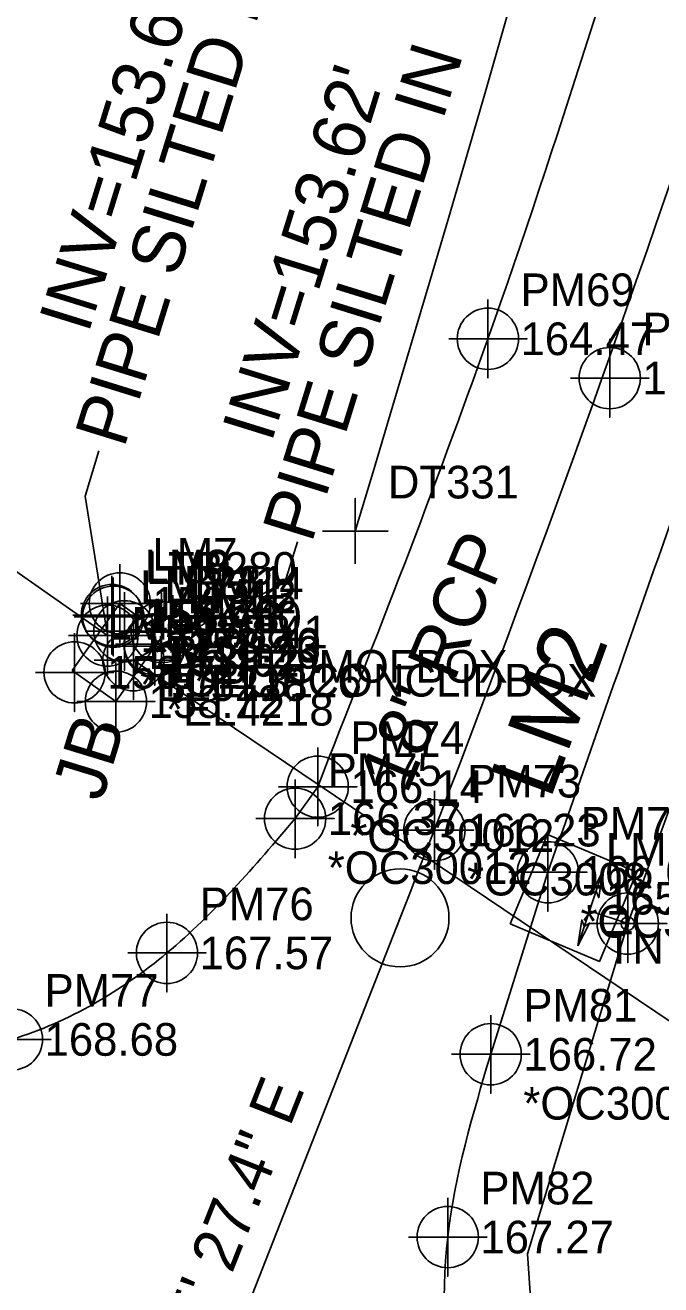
# Model space of a CAD drawing. Extents: x 2262665 to 2270527, y 505476 to 514960.
# Drawn here: x 2266229.4 to 2266278, y 509448.8 to 509545.3 of the extents above; entities that cross this region are included whole.
import ezdxf

# ---------------------------------------------------------------- set-up
doc = ezdxf.new("R2010")
doc.units = 0
for name, color, linetype in [('CTL Secondary Horizontal and Vertical CELL', 7, 'Continuous'), ('CTL Secondary Horizontal and Vertical Cogo Comment', 7, 'Continuous'), ('CTL Secondary Horizontal and Vertical Cogo Elevation', 7, 'Continuous'), ('CTL Secondary Horizontal and Vertical Cogo Number', 7, 'Continuous'), ('CTL Secondary Horizontal and Vertical Text', 7, 'Continuous'), ('Default Symbol Cogo Comment', 7, 'Continuous'), ('Default Symbol Cogo Elevation', 7, 'Continuous'), ('Default Symbol Cogo Number', 7, 'Continuous'), ('Exist DTM Crownline Cogo Comment', 7, 'Continuous'), ('Exist DTM Crownline Cogo Elevation', 7, 'Continuous'), ('Exist DTM Crownline Cogo Number', 7, 'Continuous'), ('Exist DTM Crownline Cogo Point CELL', 7, 'Continuous'), ('Exist Horizontal Alignment', 7, 'Continuous'), ('Exist Horizontal Alignment Direction Label', 7, 'Continuous'), ('Exist Roads EOP', 7, 'Continuous'), ('Exist Roads EOP Cogo Comment', 7, 'Continuous'), ('Exist Roads EOP Cogo Elevation', 7, 'Continuous'), ('Exist Roads EOP Cogo Number', 7, 'Continuous'), ('Exist Roads EOP Cogo Point CELL', 7, 'Continuous'), ('Exist Structure Minor Junction Box', 7, 'Continuous'), ('Exist Structure Minor Junction Box Cogo Comment', 7, 'Continuous'), ('Exist Structure Minor Junction Box Cogo Elevation', 7, 'Continuous'), ('Exist Structure Minor Junction Box Cogo Number', 7, 'Continuous'), ('Exist Structure Minor Junction Box Cogo Point CELL', 7, 'Continuous'), ('Exist Structure Minor Junction Box Text', 7, 'Continuous'), ('Exist Structure Minor Pipes CMP 18 Inch', 7, 'Continuous'), ('Exist Structure Minor Pipes CMP 18 Inch Cogo Comment', 7, 'Continuous'), ('Exist Structure Minor Pipes CMP 18 Inch Cogo Elevation', 7, 'Continuous'), ('Exist Structure Minor Pipes CMP 18 Inch Cogo Number', 7, 'Continuous'), ('Exist Structure Minor Pipes CMP 18 Inch Cogo Point CELL', 7, 'Continuous'), ('Exist Structure Minor Pipes CMP 18 Inch Invert', 7, 'Continuous'), ('Exist Structure Minor Pipes CMP 18 Inch Leader', 7, 'Continuous'), ('Exist Structure Minor Pipes RCP 18 Inch', 7, 'Continuous'), ('Exist Structure Minor Pipes RCP 18 Inch Cogo Comment', 7, 'Continuous'), ('Exist Structure Minor Pipes RCP 18 Inch Cogo Elevation', 7, 'Continuous'), ('Exist Structure Minor Pipes RCP 18 Inch Cogo Number', 7, 'Continuous'), ('Exist Structure Minor Pipes RCP 18 Inch Cogo Point CELL', 7, 'Continuous'), ('Exist Structure Minor Pipes RCP 18 Inch Invert', 7, 'Continuous'), ('Exist Structure Minor Pipes RCP 18 Inch Leader', 7, 'Continuous'), ('Exist Structure Minor Pipes RCP 18 Inch Text', 7, 'Continuous'), ('Exist Utilities Water Change of Service SUE CELL', 7, 'Continuous'), ('Exist Utilities Water UG Line SUE LOS B', 7, 'Continuous'), ('Exist Utilities Water UG Line SUE LOS B Cogo Point CELL', 7, 'Continuous'), ('Exist Utilities Water UG Line SUE LOS C', 7, 'Continuous'), ('Scratch_Level_1', 7, 'Continuous')]:
    doc.layers.add(name, color=color, linetype=linetype)

msp = doc.modelspace()

# ---------------------------------------------------------------- linework, layer by layer
at = {"layer": 'CTL Secondary Horizontal and Vertical CELL'}
msp.add_line((2266271.341, 509478.421), (2266271.341, 509478.421), dxfattribs=at)
msp.add_lwpolyline([(2266266.503, 509476.472), (2266269.383, 509483.302), (2266276.225, 509480.418), (2266273.345, 509473.587)], close=True, dxfattribs=at)
at = {"layer": 'Exist DTM Crownline Cogo Point CELL'}
for points in [[(2266274.139, 509521.243), (2266274.139, 509515.243), (2266274.139, 509518.243), (2266277.139, 509518.243), (2266271.139, 509518.243)], [(2266260.717, 509486.64), (2266260.717, 509480.64), (2266260.717, 509483.64), (2266263.717, 509483.64), (2266257.717, 509483.64)]]:
    msp.add_lwpolyline(points, dxfattribs=at)
for centre in [(2266274.139, 509518.243), (2266260.717, 509483.64)]:
    msp.add_circle(centre, 2.344, dxfattribs=at)
at = {"layer": 'Exist Horizontal Alignment'}
msp.add_line((2266236.663, 509422.338), (2266258.081, 509476.922), dxfattribs=at)
msp.add_circle((2266258.081, 509476.922), 3.75, dxfattribs=at)
for centre, radius, start, end in [((2263436.247, 510359.189), 2882, 309.604987, 355.646105), ((2264959.542, 509986.448), 1394.927, 338.575729, 349.591369)]:
    msp.add_arc(centre, radius, start, end, dxfattribs=at)
at = {"layer": 'Exist Roads EOP'}
for p, q in [((2266251.779, 509486.968), (2266250.048, 509484.519)), ((2266269.407, 509480.413), (2266265.025, 509466.482))]:
    msp.add_line(p, q, dxfattribs=at)
for points in [[(2266316.97, 509707.717), (2266306.122, 509661.113), (2266293.366, 509612.827), (2266279.585, 509567.039), (2266264.809, 509521.255), (2266251.779, 509486.968)], [(2266335.47, 509703.969), (2266324.499, 509656.359), (2266311.423, 509607.729), (2266297.628, 509561.395), (2266281.765, 509515.564), (2266269.407, 509480.413)], [(2266250.048, 509484.519), (2266240.238, 509474.244), (2266228.367, 509467.62), (2266215.056, 509467.121), (2266210.513, 509468.832)], [(2266265.025, 509466.482), (2266261.735, 509452.488), (2266262.146, 509437.742), (2266265.117, 509423.701), (2266271.786, 509411.222), (2266279.331, 509400.916)]]:
    msp.add_spline(points, degree=3, dxfattribs=at)
at = {"layer": 'Exist Roads EOP Cogo Point CELL'}
for points in [[(2266264.809, 509524.255), (2266264.809, 509518.255), (2266264.809, 509521.255), (2266267.809, 509521.255), (2266261.809, 509521.255)], [(2266251.779, 509489.968), (2266251.779, 509483.968), (2266251.779, 509486.968), (2266254.779, 509486.968), (2266248.779, 509486.968)], [(2266250.048, 509487.519), (2266250.048, 509481.519), (2266250.048, 509484.519), (2266253.048, 509484.519), (2266247.048, 509484.519)], [(2266269.407, 509483.413), (2266269.407, 509477.413), (2266269.407, 509480.413), (2266272.407, 509480.413), (2266266.407, 509480.413)], [(2266240.238, 509477.244), (2266240.238, 509471.244), (2266240.238, 509474.244), (2266243.238, 509474.244), (2266237.238, 509474.244)], [(2266228.367, 509470.62), (2266228.367, 509464.62), (2266228.367, 509467.62), (2266231.367, 509467.62), (2266225.367, 509467.62)], [(2266265.025, 509469.482), (2266265.025, 509463.482), (2266265.025, 509466.482), (2266268.025, 509466.482), (2266262.025, 509466.482)], [(2266261.735, 509455.488), (2266261.735, 509449.488), (2266261.735, 509452.488), (2266264.735, 509452.488), (2266258.735, 509452.488)]]:
    msp.add_lwpolyline(points, dxfattribs=at)
for centre in [(2266264.809, 509521.255), (2266251.779, 509486.968), (2266250.048, 509484.519), (2266269.407, 509480.413), (2266240.238, 509474.244), (2266228.367, 509467.62), (2266265.025, 509466.482), (2266261.735, 509452.488)]:
    msp.add_circle(centre, 2.344, dxfattribs=at)
at = {"layer": 'Exist Structure Minor Junction Box'}
msp.add_lwpolyline([(2266232.978, 509495.853), (2266236.63, 509501.002), (2266239.979, 509498.627), (2266236.327, 509493.478)], close=True, dxfattribs=at)
at = {"layer": 'Exist Structure Minor Junction Box Cogo Point CELL'}
for points in [[(2266236.63, 509504.002), (2266236.63, 509498.002), (2266236.63, 509501.002), (2266239.63, 509501.002), (2266233.63, 509501.002)], [(2266236.027, 509503.11), (2266236.027, 509497.11), (2266236.027, 509500.11), (2266239.027, 509500.11), (2266233.027, 509500.11)], [(2266236.13, 509502.981), (2266236.13, 509496.981), (2266236.13, 509499.981), (2266239.13, 509499.981), (2266233.13, 509499.981)], [(2266236.981, 509501.863), (2266236.981, 509495.863), (2266236.981, 509498.863), (2266239.981, 509498.863), (2266233.981, 509498.863)], [(2266239.83, 509501.797), (2266239.83, 509495.797), (2266239.83, 509498.797), (2266242.83, 509498.797), (2266236.83, 509498.797)], [(2266239.297, 509500.866), (2266239.297, 509494.866), (2266239.297, 509497.866), (2266242.297, 509497.866), (2266236.297, 509497.866)], [(2266239.298, 509500.734), (2266239.298, 509494.734), (2266239.298, 509497.734), (2266242.298, 509497.734), (2266236.298, 509497.734)], [(2266233.167, 509498.719), (2266233.167, 509492.719), (2266233.167, 509495.719), (2266236.167, 509495.719), (2266230.167, 509495.719)], [(2266236.327, 509496.478), (2266236.327, 509490.478), (2266236.327, 509493.478), (2266239.327, 509493.478), (2266233.327, 509493.478)]]:
    msp.add_lwpolyline(points, dxfattribs=at)
for centre in [(2266236.63, 509501.002), (2266236.027, 509500.11), (2266236.13, 509499.981), (2266236.981, 509498.863), (2266239.83, 509498.797), (2266239.297, 509497.866), (2266239.298, 509497.734), (2266233.167, 509495.719), (2266236.327, 509493.478)]:
    msp.add_circle(centre, 2.344, dxfattribs=at)
at = {"layer": 'Exist Structure Minor Pipes CMP 18 Inch'}
msp.add_line((2266235.687, 509498.531), (2266177.369, 509539.521), dxfattribs=at)
at = {"layer": 'Exist Structure Minor Pipes CMP 18 Inch Cogo Point CELL'}
msp.add_lwpolyline([(2266235.687, 509501.531), (2266235.687, 509495.531), (2266235.687, 509498.531), (2266238.687, 509498.531), (2266232.687, 509498.531)], dxfattribs=at)
msp.add_circle((2266235.687, 509498.531), 2.344, dxfattribs=at)
at = {"layer": 'Exist Structure Minor Pipes CMP 18 Inch Leader'}
msp.add_lwpolyline([(2266235.687, 509498.531), (2266233.967, 509509.21), (2266235.028, 509512.666)], dxfattribs=at)
at = {"layer": 'Exist Structure Minor Pipes RCP 18 Inch'}
msp.add_line((2266284.986, 509464.801), (2266237.667, 509496.641), dxfattribs=at)
at = {"layer": 'Exist Structure Minor Pipes RCP 18 Inch Cogo Point CELL'}
msp.add_lwpolyline([(2266237.667, 509499.641), (2266237.667, 509493.641), (2266237.667, 509496.641), (2266240.667, 509496.641), (2266234.667, 509496.641)], dxfattribs=at)
msp.add_circle((2266237.667, 509496.641), 2.344, dxfattribs=at)
at = {"layer": 'Exist Structure Minor Pipes RCP 18 Inch Leader'}
msp.add_lwpolyline([(2266237.667, 509496.641), (2266249.27, 509502.609), (2266250.221, 509505.716)], dxfattribs=at)
at = {"layer": 'Exist Utilities Water Change of Service SUE CELL'}
for p, q in [((2266273.595, 509480.442), (2266271.694, 509474.791)), ((2266272.595, 509477.471), (2266273.595, 509480.442)), ((2266275.519, 509476.487), (2266272.595, 509477.471)), ((2266275.519, 509476.487), (2266275.519, 509476.487))]:
    msp.add_line(p, q, dxfattribs=at)
for points in [[(2266273.595, 509480.442), (2266273.292, 509478.465), (2266273.101, 509478.972), (2266272.689, 509478.708)], [(2266271.694, 509474.791), (2266271.996, 509476.769), (2266272.188, 509476.261), (2266272.599, 509476.525)]]:
    msp.add_lwpolyline(points, close=True, dxfattribs=at)
msp.add_circle((2266275.519, 509476.487), 0.517, dxfattribs=at)
at = {"layer": 'Exist Utilities Water UG Line SUE LOS B'}
msp.add_lwpolyline([(2266275.519, 509476.487), (2266281.482, 509492.88), (2266288.608, 509514.277), (2266295.014, 509530.671), (2266307.182, 509564.421), (2266312.74, 509581.527), (2266318.227, 509600.174), (2266322.517, 509615.504), (2266323.024, 509617.114), (2266327.091, 509634.626), (2266333.264, 509660.071), (2266338.726, 509684.447), (2266344.641, 509710.134), (2266349.603, 509737.275), (2266354.114, 509761.833), (2266358.596, 509789.843), (2266363.318, 509817.939), (2266369.022, 509850.609), (2266373.917, 509880.477), (2266378.147, 509912.281), (2266382.035, 509940.529), (2266386.167, 509969.566), (2266389.96, 509994.369)], dxfattribs=at)
at = {"layer": 'Exist Utilities Water UG Line SUE LOS B Cogo Point CELL'}
msp.add_lwpolyline([(2266275.519, 509479.487), (2266275.519, 509473.487), (2266275.519, 509476.487), (2266278.519, 509476.487), (2266272.519, 509476.487)], dxfattribs=at)
msp.add_circle((2266275.519, 509476.487), 2.344, dxfattribs=at)
at = {"layer": 'Exist Utilities Water UG Line SUE LOS C'}
msp.add_lwpolyline([(2266274.513, 509417.088), (2266269.158, 509431.778), (2266267.846, 509451.204), (2266275.519, 509476.487)], dxfattribs=at)
at = {"layer": 'Scratch_Level_1'}
msp.add_line((2266254.653, 509506.532), (2266254.653, 509506.532), dxfattribs=at)
msp.add_lwpolyline([(2266252.153, 509506.532), (2266257.153, 509506.532), (2266254.653, 509506.532), (2266254.653, 509509.032), (2266254.653, 509504.032)], dxfattribs=at)
msp.add_arc((2263436.247, 510359.189), 2944.56, 343.167758, 355.646105, dxfattribs=at)

# ---------------------------------------------------------------- texts
at = {"layer": 'CTL Secondary Horizontal and Vertical Cogo Comment'}
msp.add_text('TN', height=2.5, dxfattribs=at).set_placement((2266273.84, 509473.431))
at = {"layer": 'CTL Secondary Horizontal and Vertical Cogo Elevation'}
msp.add_text('165.95', height=2.5, dxfattribs=at).set_placement((2266273.84, 509477.181))
at = {"layer": 'CTL Secondary Horizontal and Vertical Cogo Number'}
msp.add_text('LM2', height=2.5, dxfattribs=at).set_placement((2266273.84, 509480.931))
at = {"layer": 'CTL Secondary Horizontal and Vertical Text'}
msp.add_text('LM2', height=5, rotation=69.78629, dxfattribs=at).set_placement((2266269.572, 509485.91))
at = {"layer": 'Default Symbol Cogo Comment'}
msp.add_text('BOTTOMOFBOX', height=2.5, dxfattribs=at).set_placement((2266240.321, 509494.927))
at = {"layer": 'Default Symbol Cogo Elevation'}
msp.add_text('154.40', height=2.5, dxfattribs=at).set_placement((2266240.321, 509498.677))
at = {"layer": 'Default Symbol Cogo Number'}
msp.add_text('TB280', height=2.5, dxfattribs=at).set_placement((2266240.321, 509502.427))
at = {"layer": 'Exist DTM Crownline Cogo Comment'}
msp.add_text('*OC3008', height=2.5, dxfattribs=at).set_placement((2266263.217, 509478.64))
at = {"layer": 'Exist DTM Crownline Cogo Elevation'}
for s, p in [('164.58', (2266276.639, 509516.993)), ('166.23', (2266263.217, 509482.39))]:
    msp.add_text(s, height=2.5, dxfattribs=at).set_placement(p)
at = {"layer": 'Exist DTM Crownline Cogo Number'}
for s, p in [('PM70', (2266276.639, 509520.743)), ('PM73', (2266263.217, 509486.14))]:
    msp.add_text(s, height=2.5, dxfattribs=at).set_placement(p)
at = {"layer": 'Exist Horizontal Alignment Direction Label'}
msp.add_text('N 21%%d 25\' 27.4" E', height=3.5, rotation=68.42681, dxfattribs=at).set_placement((2266237.685, 509430.603))
at = {"layer": 'Exist Roads EOP Cogo Comment'}
for s, p in [('*OC30012', (2266254.279, 509481.968)), ('*OC30012', (2266252.548, 509479.519)), ('*OC30011', (2266271.907, 509475.413)), ('*OC30011', (2266267.525, 509461.482))]:
    msp.add_text(s, height=2.5, dxfattribs=at).set_placement(p)
at = {"layer": 'Exist Roads EOP Cogo Elevation'}
for s, p in [('164.47', (2266267.309, 509520.005)), ('166.14', (2266254.279, 509485.718)), ('166.37', (2266252.548, 509483.269)), ('166.05', (2266271.907, 509479.163)), ('167.57', (2266242.738, 509472.994)), ('168.68', (2266230.867, 509466.37)), ('166.72', (2266267.525, 509465.232)), ('167.27', (2266264.235, 509451.238))]:
    msp.add_text(s, height=2.5, dxfattribs=at).set_placement(p)
at = {"layer": 'Exist Roads EOP Cogo Number'}
for s, p in [('PM69', (2266267.309, 509523.755)), ('PM74', (2266254.279, 509489.468)), ('PM75', (2266252.548, 509487.019)), ('PM72', (2266271.907, 509482.913)), ('PM76', (2266242.738, 509476.744)), ('PM77', (2266230.867, 509470.12)), ('PM81', (2266267.525, 509468.982)), ('PM82', (2266264.235, 509454.988))]:
    msp.add_text(s, height=2.5, dxfattribs=at).set_placement(p)
at = {"layer": 'Exist Structure Minor Junction Box Cogo Comment'}
for s, p in [('*BL3126', (2266239.13, 509496.002)), ('TOPOFCONCLIDBOX', (2266239.481, 509493.863)), ('*EL3126', (2266242.33, 509493.797))]:
    msp.add_text(s, height=2.5, dxfattribs=at).set_placement(p)
at = {"layer": 'Exist Structure Minor Junction Box Cogo Elevation'}
for s, p in [('158.40', (2266238.527, 509498.86)), ('158.41', (2266239.13, 509499.752)), ('158.73', (2266238.63, 509498.731)), ('158.78', (2266239.481, 509497.613)), ('158.41', (2266242.33, 509497.547)), ('158.40', (2266241.797, 509496.616)), ('158.73', (2266241.798, 509496.484)), ('158.71', (2266235.667, 509494.469)), ('158.72', (2266238.827, 509492.228))]:
    msp.add_text(s, height=2.5, dxfattribs=at).set_placement(p)
at = {"layer": 'Exist Structure Minor Junction Box Cogo Number'}
for s, p in [('LM7', (2266239.13, 509503.502)), ('LM8', (2266238.527, 509502.61)), ('LM9', (2266238.63, 509502.481)), ('TB281', (2266239.481, 509501.363)), ('LM14', (2266242.33, 509501.297)), ('LM13', (2266241.797, 509500.366)), ('LM12', (2266241.798, 509500.234)), ('LM10', (2266235.667, 509498.219)), ('LM11', (2266238.827, 509495.978))]:
    msp.add_text(s, height=2.5, dxfattribs=at).set_placement(p)
at = {"layer": 'Exist Structure Minor Junction Box Text'}
msp.add_text('JB', height=4, rotation=72.9875, dxfattribs=at).set_placement((2266235.232, 509485.733))
at = {"layer": 'Exist Structure Minor Pipes CMP 18 Inch Cogo Comment'}
msp.add_text('*BL5218', height=2.5, dxfattribs=at).set_placement((2266238.187, 509493.531))
at = {"layer": 'Exist Structure Minor Pipes CMP 18 Inch Cogo Elevation'}
msp.add_text('153.61', height=2.5, dxfattribs=at).set_placement((2266238.187, 509497.281))
at = {"layer": 'Exist Structure Minor Pipes CMP 18 Inch Cogo Number'}
msp.add_text('LM15', height=2.5, dxfattribs=at).set_placement((2266238.187, 509501.031))
at = {"layer": 'Exist Structure Minor Pipes CMP 18 Inch Invert'}
for s, p in [("INV=153.61'", (2266234.21, 509521.577)), ('PIPE SILTED IN', (2266236.955, 509512.811))]:
    msp.add_text(s, height=4, rotation=72.76389, dxfattribs=at).set_placement(p)
at = {"layer": 'Exist Structure Minor Pipes RCP 18 Inch Cogo Comment'}
msp.add_text('*EL4218', height=2.5, dxfattribs=at).set_placement((2266240.167, 509491.641))
at = {"layer": 'Exist Structure Minor Pipes RCP 18 Inch Cogo Elevation'}
msp.add_text('153.62', height=2.5, dxfattribs=at).set_placement((2266240.167, 509495.391))
at = {"layer": 'Exist Structure Minor Pipes RCP 18 Inch Cogo Number'}
msp.add_text('LM6', height=2.5, dxfattribs=at).set_placement((2266240.167, 509499.141))
at = {"layer": 'Exist Structure Minor Pipes RCP 18 Inch Invert'}
for s, p in [('PIPE SILTED IN', (2266251.311, 509505.54)), ("INV=153.62'", (2266248.23, 509513.223))]:
    msp.add_text(s, height=4, rotation=72.76381, dxfattribs=at).set_placement(p)
at = {"layer": 'Exist Structure Minor Pipes RCP 18 Inch Text'}
msp.add_text('18" RCP', height=4, rotation=67.26915, dxfattribs=at).set_placement((2266258.603, 509486.306))
at = {"layer": 'Scratch_Level_1'}
msp.add_text('DT331', height=2.5, dxfattribs=at).set_placement((2266257.153, 509509.032))

doc.saveas('drawing.dxf')
